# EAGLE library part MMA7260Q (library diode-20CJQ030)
Freescale Semiconductor's MMA7260Q ±1.5g - 6g Three Axis Low-g Micromachined Accelerometer Description: The MMA7260Q low cost capacitive micromachined accelerometer features signal conditioning, a 1-pole low pass filter, temperature compensation and g-Select which allows for the selection among 4 sensitivities. Zero-g offset full scale span and filter cut-off are factory set and require no external devices. Includes a Sleep Mode that makes it ideal for handheld battery powered electronics. Features: Selectable Sensitivity (1.5g/2g/4g/6g) Low Current Consumption: 500 µA Sleep Mode: 3 µA Low Voltage Operation: 2.2 V  3.6 V 6mm x 6mm x 1.45mm QFN High Sensitivity (800 mV/g @1.5 g) Fast Turn On Time High Sensitivity (1.5 g) Integral Signal Conditioning with Low Pass Filter Robust Design, High Shocks Survivability Pb-Free Terminations Environmentally Preferred Package Low Cost Typical Applications: HDD MP3 Player : Freefall Detection Laptop PC : Freefall Detection, Anti-Theft Cell Phone : Image Stability, Text Scroll, Motion Dialing, E-Compass Pedometer : Motion Sensing PDA : Text Scroll Navigation and Dead Reckoning : E-Compass Tilt Compensation Gaming : Tilt and Motion Sensing, Event Recorder Robotics : Motion Sensing Please send any comments to: messi@users.sourceforge.net
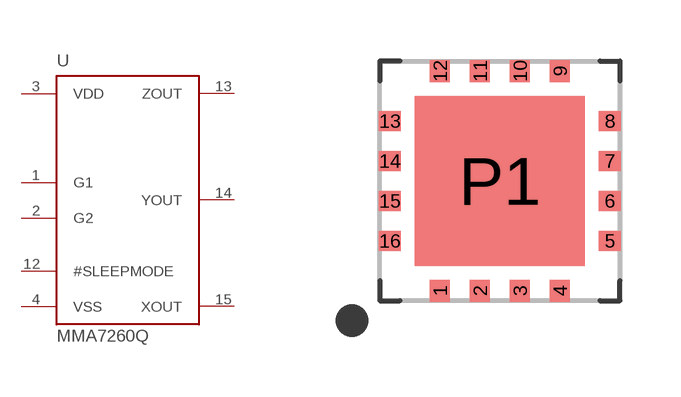
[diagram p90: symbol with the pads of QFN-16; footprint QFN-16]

Designator prefix U

## MMA7260Q  [QFN-16]
1  G1  in
2  G2  in
3  VDD  pwr
4  VSS  pwr
12  #SLEEPMODE  in
13  ZOUT  out
14  YOUT  out
15  XOUT  out

## Footprint QFN-16 (pad centres in mm)
16 LEAD QFN CASE 1622-01 E.g. MMA7260Q
smd 0.5 x 0.55: 1 -1.5,-2.75; 2 -0.5,-2.75; 3 0.5,-2.75; 4 1.5,-2.75; 9 1.5,2.75; 10 0.5,2.75; 11 -0.5,2.75; 12 -1.5,2.75
smd 0.55 x 0.5: 5 2.75,-1.5; 6 2.75,-0.5; 7 2.75,0.5; 8 2.75,1.5; 13 -2.75,1.5; 14 -2.75,0.5; 15 -2.75,-0.5; 16 -2.75,-1.5
smd 4.25 x 4.25: P1 0,0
